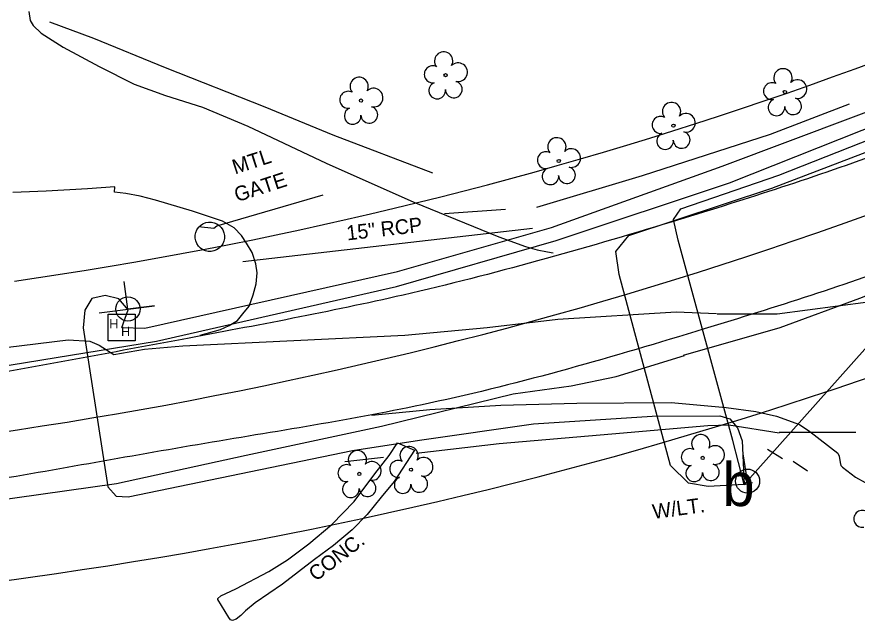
# Model space of a CAD drawing. Extents: x 1645945 to 2447332, y 713118 to 970361.
# Drawn here: x 1647146.3 to 1647317.1, y 969515.9 to 969639.7 of the extents above; entities that cross this region are included whole.
import ezdxf

# ---------------------------------------------------------------- set-up
doc = ezdxf.new("R2010")
doc.units = 0
for name, color, linetype in [('Exist Horizontal Alignment', 7, 'Continuous'), ('Exist Other Culture Area Outline', 7, 'Continuous'), ('Exist Other Culture Area Outline Text', 7, 'Continuous'), ('Exist Other Culture Fence Line', 7, 'Continuous'), ('Exist Other Culture Gate', 7, 'Continuous'), ('Exist Other Culture Gate Text', 7, 'Continuous'), ('Exist Other Culture Sign CELL', 7, 'Continuous'), ('Exist Right of Way Line', 7, 'Continuous'), ('Exist Roads EOP', 7, 'Continuous'), ('Exist Roads EOP Other', 7, 'Continuous'), ('Exist Roads Soil', 7, 'Continuous'), ('Exist Structure Minor Pipes RCP 15 Inch', 7, 'Continuous'), ('Exist Structure Minor Pipes RCP 15 Inch Text', 7, 'Continuous'), ('Exist Utilities Power Joint Use Telephone CELL', 7, 'Continuous'), ('Exist Utilities Power Pole CELL', 7, 'Continuous'), ('Exist Utilities Power Pole Text', 7, 'Continuous'), ('Exist Utilities Sanitary Sewer Forced Main SUE LOS B', 7, 'Continuous'), ('Exist Utilities Telephone Hand Hole CELL', 7, 'Continuous'), ('Exist Utilities Telephone Pedestal CELL', 7, 'Continuous'), ('Exist Utilities Telephone UG Cable SUE LOS C', 7, 'Continuous'), ('Exist Utilities Telephone UG Conduit SUE LOS B', 7, 'Continuous'), ('Exist Utilities Telephone UG FO SUE LOS C', 7, 'Continuous'), ('Exist Vegetation Tree CELL', 7, 'Continuous')]:
    doc.layers.add(name, color=color, linetype=linetype)

msp = doc.modelspace()

# ---------------------------------------------------------------- linework, layer by layer
at = {"layer": 'Exist Horizontal Alignment'}
msp.add_arc((1647013.36, 970445.89), 900, 278.18107, 298.87121, dxfattribs=at)
at = {"layer": 'Exist Other Culture Area Outline'}
msp.add_lwpolyline([(1647223.66, 969553.14), (1647227.16, 969551.63), (1647223.01, 969545.28), (1647220.4, 969542.06), (1647217.51, 969538.59), (1647214.45, 969535.48), (1647210.65, 969532.24), (1647206.81, 969529.44), (1647200.29, 969524.42), (1647194.76, 969520.63), (1647192.78, 969519.02), (1647191.88, 969518.02), (1647190.88, 969517.33), (1647190.13, 969517.01), (1647189.78, 969517.16), (1647189.39, 969517.64), (1647187.16, 969521.27), (1647187.2, 969521.51), (1647187.8, 969522.07), (1647190.86, 969523.46), (1647197.53, 969526.96), (1647201.33, 969529.39), (1647205.68, 969532.58), (1647210.33, 969536.51), (1647214.85, 969541.21), (1647219.09, 969546.8), (1647222.02, 969550.56)], close=True, dxfattribs=at)
msp.add_ellipse((1647185.54, 969594.99), major_axis=(-1.39, 2.64), ratio=0.999854, dxfattribs=at)
at = {"layer": 'Exist Other Culture Fence Line'}
for p, q in [((1647291.01, 969556.76), (1647301.25, 969555.16)), ((1647212.96, 969549.36), (1647220.85, 969550.21))]:
    msp.add_line(p, q, dxfattribs=at)
for points in [[(1647230.84, 969607.93), (1647210.58, 969615.62), (1647196.76, 969621.32), (1647176.54, 969629.34), (1647161.98, 969635.28), (1647153.04, 969638.57)], [(1647315.45, 969621.91), (1647299.4, 969615.76), (1647273.42, 969607.38), (1647251.91, 969600.96)], [(1647227.45, 969551), (1647244.38, 969553.02), (1647267.22, 969554.94), (1647286.74, 969556.63), (1647291.08, 969556.76)]]:
    msp.add_lwpolyline(points, dxfattribs=at)
at = {"layer": 'Exist Other Culture Gate'}
for p, q in [((1647245.64, 969600.51), (1647233.27, 969599.68)), ((1647301.28, 969555.28), (1647316.86, 969555.3))]:
    msp.add_line(p, q, dxfattribs=at)
msp.add_lwpolyline([(1647183.25, 969597.09), (1647186.38, 969596.72), (1647186.97, 969597.24), (1647208.58, 969603.52)], dxfattribs=at)
at = {"layer": 'Exist Other Culture Sign CELL'}
for p, q in [((1647301.95, 969549.88), (1647298.87, 969551.79)), ((1647306.99, 969547.36), (1647304.1, 969549.31))]:
    msp.add_line(p, q, dxfattribs=at)
at = {"layer": 'Exist Right of Way Line'}
msp.add_line((1646441.61, 969424.14), (1647154.4, 969526.61), dxfattribs=at)
for radius in [845, 905]:
    msp.add_arc((1647025.62, 970422.4), radius, 278.18107, 299.46236, dxfattribs=at)
at = {"layer": 'Exist Roads EOP'}
for points in [[(1647712.71, 969946.05), (1647689.83, 969906.56), (1647665.85, 969869.13), (1647637.34, 969829.12), (1647607.92, 969794.57), (1647574.53, 969760.72), (1647538.69, 969730.5), (1647499.85, 969702.79), (1647457.34, 969676.33), (1647411.66, 969651.37), (1647366.8, 969630.41), (1647321.37, 969611.83), (1647279.28, 969597.97), (1647224.82, 969583.15), (1647179.92, 969574.15), (1647132.17, 969565.53), (1647083.22, 969557.97), (1647036.22, 969550.58), (1646989.26, 969543.73)], [(1647731.3, 969935.45), (1647707.71, 969895.07), (1647684.27, 969857.13), (1647654.38, 969814.5), (1647624.46, 969779.25), (1647589.97, 969744.66), (1647553.5, 969714.01), (1647512.43, 969684.95), (1647469.3, 969658.19), (1647421.26, 969632.07), (1647375.68, 969609.9), (1647329.15, 969590.49), (1647286.02, 969576.26), (1647230.19, 969561.18), (1647183.04, 969552.75), (1647135.89, 969544.58), (1647086.4, 969536.99), (1647040.14, 969529.53), (1646992.05, 969522.32)]]:
    msp.add_spline(points, degree=3, dxfattribs=at)
at = {"layer": 'Exist Roads EOP Other'}
for points in [[(1647148.77, 969640.73), (1647149.01, 969638.95), (1647149.63, 969637.9), (1647151.24, 969636.32), (1647155.73, 969633.49), (1647163.06, 969629.6), (1647170.15, 969626.01), (1647176.57, 969623.72), (1647184.08, 969621.34), (1647193.28, 969617.47), (1647209.19, 969609.91), (1647227.04, 969601.99), (1647235.47, 969598.56), (1647244.26, 969594.99), (1647249.71, 969593.04), (1647252.08, 969592.34), (1647254.19, 969591.92), (1647255.3, 969591.75)], [(1647183.61, 969575.02), (1647187.69, 969576.12), (1647189.49, 969576.95), (1647191.14, 969577.96), (1647192.28, 969579.31), (1647193.53, 969580.9), (1647194.35, 969583.19), (1647194.98, 969585.4), (1647195.18, 969587.67), (1647194.92, 969589.51), (1647194.14, 969591.8), (1647193.03, 969593.67), (1647191.98, 969595.27), (1647190.51, 969596.78), (1647188.09, 969598.18), (1647182.01, 969600.2), (1647174.5, 969602.43), (1647171.38, 969603.21), (1647168.47, 969603.8), (1647166.18, 969604.04), (1647166.21, 969605.15), (1647160.69, 969604.73), (1647152.28, 969604.27), (1647145.5, 969604.01)]]:
    msp.add_lwpolyline(points, dxfattribs=at)
at = {"layer": 'Exist Roads Soil'}
msp.add_lwpolyline([(1647218.44, 969558.74), (1647230.28, 969559.92), (1647244.69, 969560.76), (1647260.12, 969561.2), (1647279.28, 969561.29), (1647290.49, 969560.29), (1647296.52, 969559.52), (1647300.68, 969558.54), (1647305.4, 969556.88), (1647307.46, 969555.41), (1647313.19, 969551.01), (1647313.48, 969550.42), (1647313.62, 969549.11), (1647313.78, 969548.53), (1647314.11, 969548.2), (1647316.75, 969546.14), (1647318.75, 969545.08)], dxfattribs=at)
at = {"layer": 'Exist Structure Minor Pipes RCP 15 Inch'}
msp.add_line((1647192.24, 969589.94), (1647251.1, 969596.72), dxfattribs=at)
at = {"layer": 'Exist Utilities Power Joint Use Telephone CELL'}
msp.add_line((1647168.91, 969580.31), (1647168.91, 969580.31), dxfattribs=at)
msp.add_lwpolyline([(1647163.03, 969579.52), (1647174.27, 969580.99), (1647168.91, 969580.29), (1647168.16, 969585.89)], dxfattribs=at)
msp.add_circle((1647168.91, 969580.32), 2.45, dxfattribs=at)
at = {"layer": 'Exist Utilities Power Pole CELL'}
for q in [(1647293.95, 969550.9), (1647294.83, 969545.35)]:
    msp.add_line((1647294.83, 969545.35), q, dxfattribs=at)
msp.add_circle((1647294.83, 969545.35), 2.45, dxfattribs=at)
at = {"layer": 'Exist Utilities Sanitary Sewer Forced Main SUE LOS B'}
for points in [[(1647281.82, 969570.96), (1647301.43, 969576.57), (1647317.63, 969582.51), (1647339.14, 969590.95), (1647371.77, 969606.21), (1647423.35, 969630.3), (1647468.23, 969654.45), (1647489.07, 969666.65), (1647526.6, 969691.29), (1647564.25, 969719.63), (1647582.69, 969734.56), (1647601.35, 969752.36), (1647608.99, 969759.23), (1647621.71, 969772.62)], [(1646968.01, 969517.18), (1647007.02, 969521.34), (1647054.78, 969528.26), (1647083.72, 969532.15), (1647121.99, 969538.31), (1647141.01, 969541.29), (1647166.59, 969544.9), (1647192.95, 969550.61), (1647220.41, 969556.52), (1647247.21, 969563.1), (1647258.95, 969564.71), (1647268.16, 969566.61), (1647282, 969570.9)]]:
    msp.add_lwpolyline(points, dxfattribs=at)
at = {"layer": 'Exist Utilities Telephone Hand Hole CELL'}
msp.add_lwpolyline([(1647164.91, 969579.27), (1647170.34, 969579.27), (1647170.34, 969573.84), (1647164.91, 969573.84)], close=True, dxfattribs=at)
at = {"layer": 'Exist Utilities Telephone UG Cable SUE LOS C'}
msp.add_line((1647294.11, 969544.68), (1647295.85, 969545.04), dxfattribs=at)
for points in [[(1647301.18, 969607.49), (1647346.35, 969625.33), (1647402.72, 969651.12), (1647431.08, 969666.24), (1647439.41, 969670.62), (1647442.16, 969672.78), (1647445.5, 969676.48), (1647448.63, 969678.56), (1647474.06, 969693.41), (1647520.52, 969726.92), (1647556, 969754.87), (1647590.11, 969785.42), (1647617.35, 969813.54), (1647647.46, 969852.3), (1647702.67, 969945.18), (1647775.84, 970087.47)], [(1647299.74, 969604.87), (1647344.43, 969621.93), (1647402.05, 969647.91), (1647428.7, 969661.61), (1647441.47, 969668.79), (1647444.57, 969671.27), (1647446.47, 969673.44), (1647447.93, 969674.84), (1647451.1, 969676.98), (1647475.41, 969691.19), (1647501.84, 969708.82), (1647529.96, 969729.71), (1647548.6, 969744.41), (1647576.21, 969768.81), (1647599.16, 969791.2), (1647624.94, 969819.94), (1647649.96, 969852.56), (1647680.88, 969902.23), (1647705.82, 969944.72), (1647779.36, 970085.84)], [(1647294.11, 969544.68), (1647330.92, 969585.92), (1647342.26, 969590.26), (1647406.15, 969619.43), (1647450.3, 969642.78), (1647488.96, 969665.16), (1647521.25, 969685.99), (1647545.76, 969703.5), (1647563.98, 969716.93), (1647573.87, 969725.16), (1647593.32, 969742.95), (1647627.6, 969780.32), (1647655.82, 969815.07), (1647672.99, 969839.14), (1647691.44, 969867.28), (1647722.34, 969918.27), (1647755.1, 969977.16), (1647804.4, 970074.3)], [(1647294.11, 969544.68), (1647291.83, 969553.61), (1647280.71, 969594.32), (1647279.79, 969598.5), (1647281.3, 969600.68), (1647301.18, 969607.49)], [(1647294.11, 969544.68), (1647286.83, 969544.27), (1647282.83, 969544.94), (1647279.16, 969548.5), (1647268.71, 969587.31), (1647268.09, 969591.97), (1647270.67, 969595.28), (1647299.74, 969604.87)], [(1647168.93, 969580.17), (1647167.05, 969582.4), (1647164.31, 969583.08), (1647161.58, 969582.44), (1647160.12, 969580.09), (1647159.8, 969576.47), (1647164.85, 969544.18), (1647166.49, 969542.29), (1647168.94, 969542.18), (1647214.57, 969551.55), (1647228.19, 969553.69), (1647251.34, 969557), (1647275.46, 969558.56), (1647289.19, 969558.6), (1647291.23, 969557.97), (1647292.81, 969556.19), (1647293.7, 969553.52), (1647294.11, 969544.68)]]:
    msp.add_lwpolyline(points, dxfattribs=at)
at = {"layer": 'Exist Utilities Telephone UG Conduit SUE LOS B'}
msp.add_line((1647167.63, 969576.55), (1647168.93, 969580.17), dxfattribs=at)
for points in [[(1647288.65, 969579.3), (1647300.87, 969579.36), (1647319.33, 969581.75), (1647340.65, 969587.35), (1647374.06, 969601.91), (1647427.36, 969627.15), (1647470.88, 969652.02), (1647490.61, 969664.32), (1647528.7, 969688.64), (1647565.5, 969715.45)], [(1646971.06, 969550.08), (1646972.68, 969549.64), (1646989.64, 969550.72), (1647008.61, 969553.11), (1647062.47, 969561.3), (1647091.71, 969565.17), (1647122.37, 969569.84), (1647156.76, 969574.05), (1647161.18, 969573.8), (1647163.08, 969572.94), (1647166.01, 969571.06), (1647172.25, 969572.15), (1647180.09, 969572.82), (1647225.19, 969575.03), (1647241.94, 969576.58), (1647256.28, 969578.26), (1647280.32, 969579.71), (1647288.53, 969579.4)]]:
    msp.add_lwpolyline(points, dxfattribs=at)
at = {"layer": 'Exist Utilities Telephone UG FO SUE LOS C'}
for points in [[(1647289.7, 969609.34), (1647343.59, 969629.58), (1647397.62, 969653.63), (1647450.96, 969681.88), (1647471.14, 969694.21), (1647529.28, 969736.65), (1647578.89, 969778.78), (1647616.07, 969816.36), (1647645.02, 969855.2), (1647696.33, 969943.83), (1647771.33, 970089.55)], [(1647291.19, 969605.96), (1647345.09, 969627.35), (1647401.66, 969653.17), (1647434.03, 969670.53), (1647438.26, 969672.06), (1647445.18, 969672.38), (1647450.09, 969673.09), (1647455.34, 969675.46), (1647473.43, 969686.09), (1647508.86, 969709.29), (1647532.76, 969727.04), (1647549.35, 969740.28), (1647575.78, 969764.21), (1647609.03, 969797.83), (1647638.13, 969832.64), (1647665.39, 969871.17), (1647698.7, 969925.68), (1647740.76, 970001.75), (1647782.56, 970084.37)], [(1647167.63, 969576.55), (1647172.35, 969576.45), (1647223.7, 969587.94), (1647254.96, 969596.88), (1647289.7, 969609.34)], [(1646971.06, 969550.08), (1646974.44, 969544.99), (1646978.11, 969543.87), (1646986.45, 969544.32), (1647127.62, 969566.11), (1647174.71, 969573.78), (1647223.48, 969584.86), (1647255.93, 969594.24), (1647291.19, 969605.96)]]:
    msp.add_lwpolyline(points, dxfattribs=at)
at = {"layer": 'Exist Vegetation Tree CELL'}
for p, q in [((1647233.46, 969627.82), (1647233.46, 969627.82)), ((1647302.42, 969624.4), (1647302.42, 969624.4)), ((1647216.28, 969622.66), (1647216.28, 969622.66)), ((1647279.77, 969617.56), (1647279.77, 969617.56)), ((1647256.46, 969610.39), (1647256.46, 969610.39)), ((1647285.71, 969550.06), (1647285.71, 969550.06)), ((1647215.92, 969546.82), (1647215.92, 969546.82)), ((1647226.44, 969547.67), (1647226.44, 969547.67))]:
    msp.add_line(p, q, dxfattribs=at)
for centre in [(1647233.46, 969627.82), (1647302.42, 969624.4), (1647216.28, 969622.66), (1647279.77, 969617.56), (1647256.46, 969610.39), (1647285.71, 969550.06), (1647215.92, 969546.82), (1647226.44, 969547.67)]:
    msp.add_circle(centre, 0.326, dxfattribs=at)
for centre, radius, start, end in [((1647233.07, 969630.7), 1.86, 330.1651, 219.7134), ((1647236, 969628.41), 1.9, 257.1011, 134.1999), ((1647230.85, 969627.98), 1.73, 62.6636, 279.3457), ((1647302.03, 969627.28), 1.86, 330.1651, 219.7134), ((1647215.9, 969625.53), 1.86, 330.1651, 219.7134), ((1647304.97, 969624.99), 1.9, 257.1011, 134.1999), ((1647218.83, 969623.25), 1.9, 257.1011, 134.1999), ((1647231.75, 969624.7), 1.69, 111.5671, 6.231), ((1647235.13, 969624.92), 1.7, 181.2822, 74.56), ((1647299.81, 969624.56), 1.73, 62.6636, 279.3457), ((1647213.68, 969622.81), 1.73, 62.6636, 279.3457), ((1647279.38, 969620.43), 1.86, 330.1651, 219.7134), ((1647300.71, 969621.28), 1.69, 111.5671, 6.231), ((1647304.09, 969621.5), 1.7, 181.2822, 74.56), ((1647214.58, 969619.54), 1.69, 111.5671, 6.231), ((1647217.96, 969619.76), 1.7, 181.2822, 74.56), ((1647282.31, 969618.15), 1.9, 257.1011, 134.1999), ((1647277.16, 969617.71), 1.73, 62.6636, 279.3457), ((1647256.08, 969613.26), 1.86, 330.1651, 219.7134), ((1647278.06, 969614.44), 1.69, 111.5671, 6.231), ((1647281.44, 969614.66), 1.7, 181.2822, 74.56), ((1647253.85, 969610.54), 1.73, 62.6636, 279.3457), ((1647259.01, 969610.98), 1.9, 257.1011, 134.1999), ((1647254.76, 969607.27), 1.69, 111.5671, 6.231), ((1647258.13, 969607.49), 1.7, 181.2822, 74.56), ((1647285.32, 969552.94), 1.86, 330.1651, 219.7134), ((1647226.05, 969550.54), 1.86, 330.1651, 219.7134), ((1647283.1, 969550.22), 1.73, 62.6636, 279.3457), ((1647288.26, 969550.65), 1.9, 257.1011, 134.1999), ((1647215.54, 969549.69), 1.86, 330.1651, 219.7134), ((1647228.99, 969548.26), 1.9, 257.1011, 134.1999), ((1647213.32, 969546.97), 1.73, 62.6636, 279.3457), ((1647218.47, 969547.41), 1.9, 257.1011, 134.1999), ((1647223.83, 969547.82), 1.73, 62.6636, 279.3457), ((1647284, 969546.94), 1.69, 111.5671, 6.231), ((1647287.38, 969547.16), 1.7, 181.2822, 74.56), ((1647214.22, 969543.7), 1.69, 111.5671, 6.231), ((1647217.6, 969543.92), 1.7, 181.2822, 74.56), ((1647224.73, 969544.55), 1.69, 111.5671, 6.231), ((1647228.11, 969544.77), 1.7, 181.2822, 74.56), ((1647318.15, 969537.68), 1.73, 62.6636, 279.3457)]:
    msp.add_arc(centre, radius, start, end, dxfattribs=at)

# ---------------------------------------------------------------- texts
at = {"layer": 'Exist Other Culture Area Outline Text'}
msp.add_text('CONC.', height=3, rotation=37.764, dxfattribs=at).set_placement((1647207.1, 969524.86))
at = {"layer": 'Exist Other Culture Gate Text'}
for s, p in [('MTL', (1647190.66, 969607.65)), ('GATE', (1647191.08, 969602))]:
    msp.add_text(s, height=3, rotation=17.887, dxfattribs=at).set_placement(p)
at = {"layer": 'Exist Structure Minor Pipes RCP 15 Inch Text'}
msp.add_text('15" RCP', height=3, rotation=6.5663, dxfattribs=at).set_placement((1647213.48, 969594.24))
at = {"layer": 'Exist Utilities Power Pole Text'}
msp.add_text('W/LT.', height=3, rotation=7.7882, dxfattribs=at).set_placement((1647275.71, 969537.64))
at = {"layer": 'Exist Utilities Telephone Hand Hole CELL'}
for p in [(1647166.98, 969578.31), (1647169.36, 969576.75)]:
    msp.add_text('H', height=1.94, rotation=180, dxfattribs=at).set_placement(p)
at = {"layer": 'Exist Utilities Telephone Pedestal CELL'}
msp.add_text('b', height=8.81, dxfattribs=at).set_placement((1647289.71, 969540.28))

doc.saveas('drawing.dxf')
